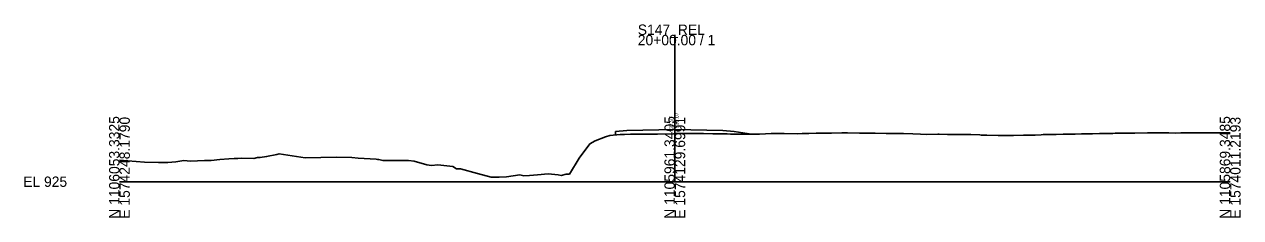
# Model space of a CAD drawing. Extents: x 1557985 to 1558314, y 1113650 to 1118205.
# Drawn here: x 1557985.4 to 1558314, y 1117150.1 to 1117202.2 of the extents above; entities that cross this region are included whole.
import ezdxf

# ---------------------------------------------------------------- set-up
doc = ezdxf.new("R2010")
doc.units = 0
for name, color, linetype in [('RD_GPK_XS_Cell', 7, 'Continuous'), ('RD_XS_EarthShd', 7, 'Continuous'), ('RD_XS_ExGround', 7, 'Continuous'), ('RD_XS_Pave', 7, 'Continuous'), ('RD_XS_TieSlope', 7, 'Continuous'), ('RD_XS_TX_Elev_EX', 7, 'Continuous'), ('RD_XS_TX_Elev_PR', 7, 'Continuous')]:
    doc.layers.add(name, color=color, linetype=linetype)

msp = doc.modelspace()

# ---------------------------------------------------------------- linework, layer by layer
at = {"layer": 'RD_GPK_XS_Cell'}
for p, q in [((1558161.13, 1117159.8), (1558161.13, 1117199.4)), ((1558011.13, 1117159.8), (1558161.13, 1117159.8)), ((1558161.13, 1117159.8), (1558311.13, 1117159.8))]:
    msp.add_line(p, q, dxfattribs=at)
at = {"layer": 'RD_XS_EarthShd'}
for p, q in [((1558148.13, 1117173.61), (1558145.13, 1117173.37)), ((1558174.13, 1117173.61), (1558177.13, 1117173.37))]:
    msp.add_line(p, q, dxfattribs=at)
at = {"layer": 'RD_XS_ExGround'}
msp.add_lwpolyline([(1558011.13, 1117165.63), (1558017.86, 1117165.04), (1558021.68, 1117164.99), (1558022.92, 1117164.98), (1558023.4, 1117164.99), (1558024.15, 1117164.97), (1558026.37, 1117165.14), (1558028.54, 1117165.48), (1558030.33, 1117165.36), (1558034.09, 1117165.53), (1558035.93, 1117165.54), (1558038.26, 1117165.8), (1558040.63, 1117165.95), (1558042.15, 1117166.03), (1558043.07, 1117166.04), (1558044.1, 1117166.19), (1558047.38, 1117166.03), (1558048.38, 1117166.37), (1558049.17, 1117166.35), (1558050.86, 1117166.59), (1558053.6, 1117167.17), (1558054.29, 1117167.29), (1558061.33, 1117166.25), (1558069.78, 1117166.45), (1558073.89, 1117166.31), (1558075.57, 1117166.13), (1558080.5, 1117165.87), (1558080.81, 1117165.83), (1558081.15, 1117165.76), (1558082.3, 1117165.5), (1558089.18, 1117165.53), (1558090.75, 1117165.34), (1558094.16, 1117164.39), (1558095.45, 1117164.16), (1558097.15, 1117164.32), (1558101.14, 1117163.93), (1558102.16, 1117163.3), (1558103.28, 1117163.24), (1558107.86, 1117162.05), (1558111.5, 1117161), (1558112.8, 1117161.02), (1558113.69, 1117161.05), (1558115.7, 1117161.15), (1558119.3, 1117161.61), (1558120.36, 1117161.41), (1558121.91, 1117161.43), (1558124.03, 1117161.67), (1558126.96, 1117161.95), (1558129.64, 1117161.61), (1558130.46, 1117161.46), (1558131.81, 1117161.86), (1558132.68, 1117161.87), (1558135.3, 1117166.18), (1558138.2, 1117170.05), (1558139.58, 1117170.86), (1558142.42, 1117171.92), (1558143.6, 1117172.28), (1558146.39, 1117172.49), (1558147.2, 1117172.57), (1558147.57, 1117172.57), (1558149.2, 1117172.58), (1558151.88, 1117172.58), (1558153.52, 1117172.62), (1558154.62, 1117172.63), (1558155.34, 1117172.65), (1558156.43, 1117172.66), (1558160.74, 1117172.75), (1558161.13, 1117172.76), (1558163.94, 1117172.8), (1558165.85, 1117172.79), (1558166.44, 1117172.79), (1558168.87, 1117172.78), (1558171.36, 1117172.72), (1558172.07, 1117172.73), (1558172.79, 1117172.72), (1558175.24, 1117172.67), (1558176.17, 1117172.64), (1558179.27, 1117172.63), (1558180.56, 1117172.61), (1558181.35, 1117172.61), (1558183.96, 1117172.61), (1558185.63, 1117172.73), (1558187.14, 1117172.81), (1558188.09, 1117172.79), (1558190.69, 1117172.78), (1558194.23, 1117172.74), (1558195.52, 1117172.78), (1558197.34, 1117172.84), (1558199.3, 1117172.87), (1558200.79, 1117172.9), (1558201.39, 1117172.88), (1558202.52, 1117172.89), (1558203.43, 1117172.88), (1558206.27, 1117172.98), (1558207.76, 1117172.95), (1558211.05, 1117172.91), (1558211.95, 1117172.93), (1558213.14, 1117172.93), (1558215.23, 1117172.91), (1558218.25, 1117172.8), (1558218.68, 1117172.79), (1558219.27, 1117172.79), (1558220.8, 1117172.8), (1558222.9, 1117172.82), (1558225.39, 1117172.7), (1558227.48, 1117172.63), (1558229.1, 1117172.56), (1558232.18, 1117172.6), (1558232.54, 1117172.59), (1558234.81, 1117172.56), (1558236.56, 1117172.54), (1558237.23, 1117172.53), (1558238.22, 1117172.51), (1558240.62, 1117172.52), (1558241.05, 1117172.5), (1558243.54, 1117172.41), (1558243.91, 1117172.39), (1558245.39, 1117172.32), (1558248.51, 1117172.24), (1558250.07, 1117172.25), (1558250.61, 1117172.26), (1558252.65, 1117172.24), (1558255.32, 1117172.31), (1558256.22, 1117172.31), (1558256.79, 1117172.33), (1558258.15, 1117172.36), (1558258.49, 1117172.37), (1558260.06, 1117172.48), (1558260.63, 1117172.51), (1558263.65, 1117172.55), (1558264.16, 1117172.56), (1558266.05, 1117172.6), (1558268.76, 1117172.62), (1558269.3, 1117172.63), (1558270.94, 1117172.68), (1558273.21, 1117172.71), (1558273.98, 1117172.73), (1558275.87, 1117172.77), (1558279.42, 1117172.82), (1558280.08, 1117172.85), (1558280.81, 1117172.86), (1558281.36, 1117172.87), (1558282.16, 1117172.87), (1558282.79, 1117172.85), (1558284.1, 1117172.87), (1558285.36, 1117172.86), (1558288.84, 1117172.95), (1558289.87, 1117172.97), (1558290.68, 1117172.99), (1558292.77, 1117172.96), (1558293.62, 1117172.96), (1558294.53, 1117172.95), (1558296.46, 1117172.93), (1558297.8, 1117172.94), (1558299.72, 1117172.94), (1558301.43, 1117172.99), (1558303.14, 1117173), (1558304.79, 1117172.98), (1558307.02, 1117172.97), (1558307.62, 1117172.97), (1558311.13, 1117172.96)], dxfattribs=at)
at = {"layer": 'RD_XS_Pave'}
for p, q in [((1558161.13, 1117173.87), (1558148.13, 1117173.61)), ((1558174.13, 1117173.61), (1558161.13, 1117173.87))]:
    msp.add_line(p, q, dxfattribs=at)
at = {"layer": 'RD_XS_TieSlope'}
for p, q in [((1558145.13, 1117173.37), (1558145.13, 1117172.4)), ((1558177.13, 1117173.37), (1558181.86, 1117172.61))]:
    msp.add_line(p, q, dxfattribs=at)

# ---------------------------------------------------------------- texts
at = {"layer": 'RD_GPK_XS_Cell'}
for s, p in [('S147_REL', (1558151.13, 1117199.4)), ('20+00.00 / 1', (1558151.13, 1117196.6)), ('EL 925', (1557985.13, 1117158.4))]:
    msp.add_text(s, height=2.8, dxfattribs=at).set_placement(p)
for s, p in [('N 1106053.3325', (1558011.13, 1117149.8)), ('E 1574248.1790', (1558013.93, 1117149.8)), ('N 1105961.3405', (1558161.13, 1117149.8)), ('E 1574129.6991', (1558163.93, 1117149.8)), ('N 1105869.3485', (1558311.13, 1117149.8)), ('E 1574011.2193', (1558313.93, 1117149.8))]:
    msp.add_text(s, height=2.8, rotation=90, dxfattribs=at).set_placement(p)
at = {"layer": 'RD_XS_TX_Elev_EX'}
msp.add_text('937.97', height=1, rotation=90, dxfattribs=at).set_placement((1558160.63, 1117173.26))
at = {"layer": 'RD_XS_TX_Elev_PR'}
msp.add_text(' 939.07', height=1, rotation=90, dxfattribs=at).set_placement((1558162.13, 1117173.87))

doc.saveas('drawing.dxf')
